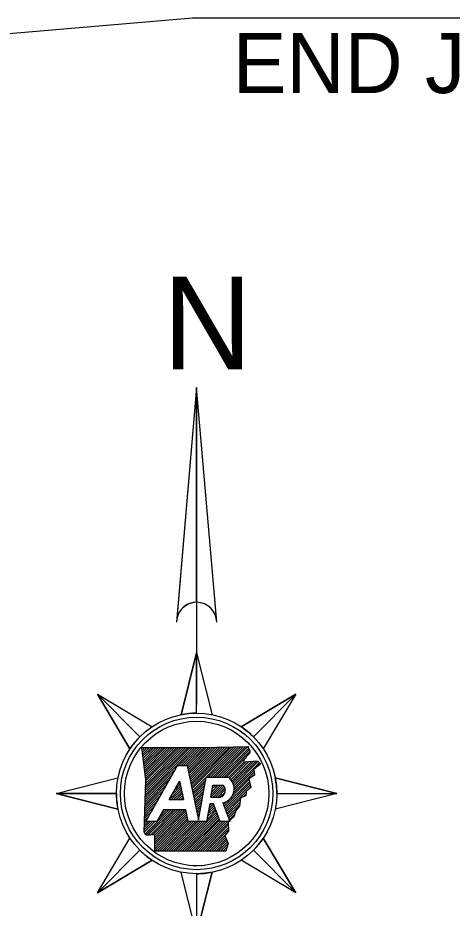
# Model space of a CAD drawing. Extents: x 1367863 to 1368197, y 380048 to 380261.
# Drawn here: x 1368103.87 to 1368125.53, y 380096.4 to 380140.77 of the extents above; entities that cross this region are included whole.
import ezdxf

# ---------------------------------------------------------------- set-up
doc = ezdxf.new("R2010")
doc.units = 0
doc.layers.add('R_Draft', color=7, linetype='Continuous')
doc.layers.add('R_Water Annot', color=7, linetype='Continuous')

msp = doc.modelspace()

# ---------------------------------------------------------------- linework, layer by layer
at = {"layer": 'R_Draft'}
for p, q in [((1368112.592, 380140.769), (1368153.505, 380140.769)), ((1368112.79, 380122.345), (1368111.804, 380110.815)), ((1368112.79, 380122.345), (1368112.79, 380106.554)), ((1368112.79, 380111.645), (1368112.79, 380122.345)), ((1368111.823, 380111.038), (1368111.915, 380111.129)), ((1368111.818, 380110.976), (1368111.863, 380111.021)), ((1368112.79, 380109.117), (1368112.011, 380106.041)), ((1368112.79, 380106.117), (1368112.79, 380109.117)), ((1368107.84, 380107.067), (1368109.961, 380104.946)), ((1368109.961, 380104.946), (1368107.84, 380107.067)), ((1368107.84, 380107.067), (1368109.465, 380104.341)), ((1368117.74, 380107.067), (1368115.013, 380105.442)), ((1368115.618, 380104.946), (1368117.74, 380107.067)), ((1368115.618, 380104.946), (1368117.74, 380107.067)), ((1368110.264, 380100.716), (1368111.842, 380103.503)), ((1368111.842, 380103.503), (1368112.311, 380103.503)), ((1368111.425, 380101.81), (1368111.941, 380102.722)), ((1368113.263, 380102.922), (1368114.359, 380102.922)), ((1368119.79, 380102.117), (1368116.713, 380102.896)), ((1368113.604, 380102.528), (1368114.119, 380102.528)), ((1368105.79, 380102.117), (1368108.79, 380102.117)), ((1368108.79, 380102.117), (1368105.79, 380102.117)), ((1368105.79, 380102.117), (1368108.866, 380101.338)), ((1368111.425, 380101.81), (1368112.136, 380101.81)), ((1368113.501, 380101.933), (1368113.971, 380101.933)), ((1368116.79, 380102.117), (1368119.79, 380102.117)), ((1368116.79, 380102.117), (1368119.79, 380102.117)), ((1368113.633, 380101.602), (1368113.443, 380101.602)), ((1368113.96, 380100.716), (1368113.633, 380101.602)), ((1368114.097, 380101.65), (1368114.442, 380100.716)), ((1368111.136, 380101.301), (1368110.805, 380100.716)), ((1368112.245, 380101.301), (1368111.136, 380101.301)), ((1368110.805, 380100.716), (1368110.264, 380100.716)), ((1368113.289, 380100.716), (1368112.37, 380100.716)), ((1368114.442, 380100.716), (1368113.96, 380100.716)), ((1368117.74, 380097.167), (1368116.115, 380099.894)), ((1368107.84, 380097.167), (1368109.961, 380099.289)), ((1368109.961, 380099.289), (1368107.84, 380097.167)), ((1368115.618, 380099.289), (1368117.74, 380097.167)), ((1368115.618, 380099.289), (1368117.74, 380097.167)), ((1368107.84, 380097.167), (1368110.566, 380098.792)), ((1368112.79, 380095.117), (1368113.569, 380098.194)), ((1368112.79, 380098.117), (1368112.79, 380098.117)), ((1368112.79, 380098.117), (1368112.79, 380085.312)), ((1368112.79, 380098.117), (1368112.79, 380095.117))]:
    msp.add_line(p, q, dxfattribs=at)
for points in [[(1368073.255, 380137.414), (1368112.592, 380140.769)], [(1368113.79, 380110.645), (1368112.79, 380122.345), (1368111.79, 380110.645)], [(1368112.011, 380106.041), (1368112.79, 380109.117), (1368113.569, 380106.041)], [(1368109.465, 380104.341), (1368107.84, 380107.067), (1368110.566, 380105.442)], [(1368115.013, 380105.442), (1368117.74, 380107.067), (1368116.115, 380104.341)], [(1368110.059, 380104.407), (1368111.62, 380104.406), (1368112.99, 380104.409), (1368114.605, 380104.434), (1368115.354, 380104.451)], [(1368110.172, 380100.184), (1368110.259, 380102.803), (1368110.059, 380104.407)], [(1368115.845, 380103.734), (1368115.98, 380103.593), (1368115.643, 380103.316), (1368115.679, 380103.037), (1368115.391, 380102.846), (1368115.49, 380102.417), (1368115.267, 380102.214), (1368115.247, 380101.993), (1368114.976, 380101.895), (1368114.934, 380101.479), (1368114.74, 380101.271), (1368114.646, 380100.957), (1368114.362, 380100.698), (1368114.384, 380100.24), (1368114.191, 380100.024), (1368114.367, 380099.632), (1368114.245, 380099.242)], [(1368115.123, 380103.698), (1368115.855, 380103.735)], [(1368112.311, 380103.503), (1368112.891, 380100.79), (1368113.263, 380102.922)], [(1368108.866, 380101.338), (1368105.79, 380102.117), (1368108.866, 380102.896)], [(1368111.941, 380102.722), (1368112.136, 380101.81)], [(1368116.713, 380102.896), (1368119.79, 380102.117), (1368116.713, 380101.338)], [(1368113.501, 380101.933), (1368113.604, 380102.528)], [(1368113.443, 380101.602), (1368113.289, 380100.716)], [(1368112.37, 380100.716), (1368112.245, 380101.301)], [(1368114.245, 380099.242), (1368110.708, 380099.248), (1368110.706, 380100.029)], [(1368110.566, 380098.792), (1368107.84, 380097.167), (1368109.465, 380099.894)], [(1368116.115, 380099.894), (1368117.74, 380097.167), (1368115.013, 380098.792)], [(1368113.569, 380098.194), (1368112.79, 380095.117), (1368112.011, 380098.194)]]:
    msp.add_lwpolyline(points, dxfattribs=at)
for radius in [4, 3.6]:
    msp.add_circle((1368112.79, 380102.117), radius, dxfattribs=at)
for centre, radius, start, end in [((1368112.79, 380110.645), 1, 0, 180), ((1368112.79, 380110.645), 1, 90, 170.2296), ((1368112.79, 380102.117), 4, 90, 101.2291), ((1368112.79, 380102.117), 4, 45, 56.2291), ((1368112.79, 380102.117), 4, 135, 146.2291), ((1368113.951, 380102.343), 0.708, 281.8626, 54.8705), ((1368112.79, 380102.117), 4, 0, 11.2291), ((1368113.858, 380102.277), 0.362, 288.1268, 43.8902), ((1368112.79, 380102.117), 4, 180, 191.2291), ((1368112.79, 380102.117), 4, 315, 326.2291), ((1368112.79, 380102.117), 4, 225, 236.2291), ((1368112.79, 380102.117), 4, 270, 281.2291)]:
    msp.add_arc(centre, radius, start, end, dxfattribs=at)
for points in [[(1368115.354, 380104.451), (1368115.359, 380104.409), (1368115.373, 380104.387), (1368115.375, 380104.346), (1368115.391, 380104.329), (1368115.419, 380104.311), (1368115.444, 380104.283), (1368115.45, 380104.251), (1368115.442, 380104.217), (1368115.44, 380104.179), (1368115.436, 380104.146), (1368115.431, 380104.116), (1368115.408, 380104.092), (1368115.385, 380104.075), (1368115.365, 380104.055), (1368115.351, 380104.033), (1368115.325, 380104.01), (1368115.3, 380103.986), (1368115.28, 380103.965), (1368115.26, 380103.938), (1368115.25, 380103.908), (1368115.228, 380103.887), (1368115.211, 380103.867), (1368115.187, 380103.841), (1368115.176, 380103.815), (1368115.154, 380103.785), (1368115.149, 380103.756), (1368115.134, 380103.733), (1368115.133, 380103.729)], [(1368110.706, 380100.029), (1368110.71, 380100.027), (1368110.691, 380100.039), (1368110.666, 380100.052), (1368110.638, 380100.054), (1368110.602, 380100.058), (1368110.572, 380100.061), (1368110.542, 380100.082), (1368110.509, 380100.06), (1368110.472, 380100.045), (1368110.451, 380100.062), (1368110.423, 380100.051), (1368110.404, 380100.057), (1368110.37, 380100.033), (1368110.338, 380100.042), (1368110.315, 380100.035), (1368110.286, 380100.036), (1368110.28, 380100.069), (1368110.252, 380100.074), (1368110.228, 380100.087), (1368110.211, 380100.121), (1368110.2, 380100.147), (1368110.172, 380100.184)]]:
    msp.add_spline(points, degree=3, dxfattribs=at)
at = {"layer": 'R_Water Annot'}
for p, q in [((1368112.42, 380102.995), (1368113.847, 380104.422)), ((1368112.44, 380102.901), (1368113.962, 380104.424)), ((1368112.46, 380102.808), (1368114.077, 380104.426)), ((1368112.48, 380102.715), (1368114.192, 380104.428)), ((1368112.499, 380102.622), (1368114.307, 380104.429)), ((1368112.519, 380102.529), (1368114.422, 380104.431)), ((1368112.539, 380102.435), (1368114.537, 380104.433)), ((1368112.559, 380102.342), (1368114.652, 380104.435)), ((1368112.579, 380102.249), (1368114.768, 380104.438)), ((1368113.365, 380102.922), (1368114.884, 380104.44)), ((1368113.478, 380102.922), (1368115, 380104.443)), ((1368113.591, 380102.922), (1368115.116, 380104.446)), ((1368113.705, 380102.922), (1368115.231, 380104.449)), ((1368113.818, 380102.922), (1368115.347, 380104.451)), ((1368110.063, 380104.372), (1368110.099, 380104.407)), ((1368110.076, 380104.271), (1368110.212, 380104.407)), ((1368110.088, 380104.17), (1368110.325, 380104.407)), ((1368110.101, 380104.07), (1368110.438, 380104.407)), ((1368110.113, 380103.969), (1368110.551, 380104.407)), ((1368110.126, 380103.869), (1368110.664, 380104.407)), ((1368110.139, 380103.768), (1368110.777, 380104.407)), ((1368110.151, 380103.667), (1368110.89, 380104.406)), ((1368110.164, 380103.567), (1368111.003, 380104.406)), ((1368110.176, 380103.466), (1368111.116, 380104.406)), ((1368110.189, 380103.366), (1368111.229, 380104.406)), ((1368110.201, 380103.265), (1368111.342, 380104.406)), ((1368110.214, 380103.164), (1368111.455, 380104.406)), ((1368110.226, 380103.064), (1368111.568, 380104.406)), ((1368110.23, 380101.936), (1368112.702, 380104.408)), ((1368110.234, 380102.053), (1368112.589, 380104.408)), ((1368110.238, 380102.17), (1368112.475, 380104.408)), ((1368110.239, 380102.963), (1368111.682, 380104.406)), ((1368110.242, 380102.287), (1368112.362, 380104.408)), ((1368110.246, 380102.404), (1368112.249, 380104.407)), ((1368110.249, 380102.521), (1368112.135, 380104.407)), ((1368110.251, 380102.863), (1368111.795, 380104.406)), ((1368110.253, 380102.638), (1368112.022, 380104.407)), ((1368110.257, 380102.755), (1368111.908, 380104.407)), ((1368111.91, 380103.503), (1368112.815, 380104.409)), ((1368112.023, 380103.503), (1368112.929, 380104.409)), ((1368112.136, 380103.503), (1368113.043, 380104.41)), ((1368112.25, 380103.503), (1368113.158, 380104.412)), ((1368112.32, 380103.461), (1368113.273, 380104.413)), ((1368112.34, 380103.367), (1368113.388, 380104.415)), ((1368112.36, 380103.274), (1368113.503, 380104.417)), ((1368112.38, 380103.181), (1368113.618, 380104.419)), ((1368112.4, 380103.088), (1368113.733, 380104.42)), ((1368113.931, 380102.922), (1368115.372, 380104.363)), ((1368114.044, 380102.922), (1368115.427, 380104.305)), ((1368114.157, 380102.922), (1368115.442, 380104.206)), ((1368114.27, 380102.922), (1368115.183, 380103.835)), ((1368114.373, 380102.911), (1368115.161, 380103.7)), ((1368114.435, 380102.86), (1368115.28, 380103.706)), ((1368114.49, 380102.802), (1368115.4, 380103.712)), ((1368114.539, 380102.738), (1368115.519, 380103.718)), ((1368114.581, 380102.667), (1368115.638, 380103.724)), ((1368114.615, 380102.588), (1368115.757, 380103.73)), ((1368114.641, 380102.501), (1368115.865, 380103.724)), ((1368114.657, 380102.403), (1368115.918, 380103.664)), ((1368115.868, 380103.501), (1368115.971, 380103.604)), ((1368110.226, 380101.819), (1368111.753, 380103.346)), ((1368114.634, 380102.154), (1368115.661, 380103.181)), ((1368114.658, 380102.291), (1368115.648, 380103.281)), ((1368110.218, 380101.585), (1368111.457, 380102.824)), ((1368110.222, 380101.702), (1368111.605, 380103.085)), ((1368111.861, 380102.58), (1368111.952, 380102.671)), ((1368112.599, 380102.156), (1368113.241, 380102.798)), ((1368112.619, 380102.063), (1368113.217, 380102.661)), ((1368114.167, 380101.461), (1368115.421, 380102.715)), ((1368114.535, 380101.942), (1368115.4, 380102.807)), ((1368115.534, 380102.941), (1368115.674, 380103.081)), ((1368110.211, 380101.351), (1368111.162, 380102.303)), ((1368110.214, 380101.468), (1368111.31, 380102.563)), ((1368111.43, 380101.81), (1368112.011, 380102.391)), ((1368111.543, 380101.81), (1368112.031, 380102.298)), ((1368111.565, 380102.058), (1368111.992, 380102.485)), ((1368111.656, 380101.81), (1368112.051, 380102.205)), ((1368111.713, 380102.319), (1368111.972, 380102.578)), ((1368112.639, 380101.969), (1368113.193, 380102.524)), ((1368112.659, 380101.876), (1368113.17, 380102.387)), ((1368112.679, 380101.783), (1368113.146, 380102.25)), ((1368113.501, 380101.933), (1368114.097, 380102.528)), ((1368113.524, 380102.069), (1368113.983, 380102.528)), ((1368113.548, 380102.206), (1368113.87, 380102.528)), ((1368113.572, 380102.343), (1368113.757, 380102.528)), ((1368113.596, 380102.48), (1368113.644, 380102.528)), ((1368113.614, 380101.933), (1368114.159, 380102.478)), ((1368113.728, 380101.933), (1368114.198, 380102.403)), ((1368113.841, 380101.933), (1368114.219, 380102.311)), ((1368114.197, 380101.378), (1368115.442, 380102.623)), ((1368114.228, 380101.295), (1368115.463, 380102.531)), ((1368114.258, 380101.213), (1368115.484, 380102.439)), ((1368110.203, 380101.117), (1368110.867, 380101.781)), ((1368110.207, 380101.234), (1368111.014, 380102.042)), ((1368111.769, 380101.81), (1368112.071, 380102.112)), ((1368111.883, 380101.81), (1368112.091, 380102.019)), ((1368111.996, 380101.81), (1368112.111, 380101.925)), ((1368112.109, 380101.81), (1368112.131, 380101.832)), ((1368112.699, 380101.69), (1368113.122, 380102.113)), ((1368112.719, 380101.597), (1368113.098, 380101.976)), ((1368112.739, 380101.503), (1368113.074, 380101.839)), ((1368113.954, 380101.933), (1368114.209, 380102.188)), ((1368114.289, 380101.13), (1368114.968, 380101.809)), ((1368115.098, 380101.939), (1368115.256, 380102.098)), ((1368110.199, 380101), (1368110.719, 380101.52)), ((1368112.759, 380101.41), (1368113.05, 380101.702)), ((1368112.779, 380101.317), (1368113.026, 380101.565)), ((1368112.799, 380101.224), (1368113.002, 380101.428)), ((1368113.332, 380100.965), (1368113.724, 380101.357)), ((1368113.356, 380101.102), (1368113.693, 380101.44)), ((1368113.38, 380101.239), (1368113.663, 380101.522)), ((1368113.404, 380101.376), (1368113.63, 380101.602)), ((1368113.427, 380101.513), (1368113.517, 380101.602)), ((1368114.106, 380101.626), (1368114.14, 380101.66)), ((1368114.136, 380101.543), (1368114.352, 380101.759)), ((1368114.319, 380101.048), (1368114.955, 380101.683)), ((1368114.35, 380100.965), (1368114.942, 380101.557)), ((1368110.191, 380100.766), (1368110.424, 380100.998)), ((1368110.195, 380100.883), (1368110.571, 380101.259)), ((1368110.216, 380100.112), (1368111.405, 380101.301)), ((1368110.283, 380100.066), (1368111.518, 380101.301)), ((1368110.364, 380100.034), (1368111.631, 380101.301)), ((1368110.499, 380100.055), (1368111.744, 380101.301)), ((1368110.613, 380100.057), (1368111.857, 380101.301)), ((1368110.702, 380100.032), (1368111.97, 380101.301)), ((1368110.706, 380099.81), (1368112.197, 380101.301)), ((1368110.706, 380099.923), (1368112.084, 380101.301)), ((1368110.706, 380099.697), (1368112.256, 380101.247)), ((1368110.707, 380099.585), (1368112.276, 380101.154)), ((1368110.707, 380099.472), (1368112.296, 380101.061)), ((1368110.707, 380099.359), (1368112.316, 380100.968)), ((1368110.709, 380099.248), (1368112.336, 380100.874)), ((1368110.933, 380100.943), (1368111.292, 380101.301)), ((1368111.081, 380101.203), (1368111.179, 380101.301)), ((1368111.839, 380099.246), (1368113.785, 380101.192)), ((1368111.952, 380099.246), (1368113.815, 380101.109)), ((1368112.065, 380099.245), (1368113.846, 380101.026)), ((1368112.178, 380099.245), (1368113.876, 380100.944)), ((1368112.819, 380101.131), (1368112.979, 380101.291)), ((1368112.839, 380101.037), (1368112.955, 380101.154)), ((1368112.858, 380100.944), (1368112.931, 380101.017)), ((1368112.878, 380100.851), (1368112.907, 380100.88)), ((1368113.308, 380100.828), (1368113.754, 380101.274)), ((1368114.38, 380100.882), (1368114.727, 380101.229)), ((1368114.411, 380100.8), (1368114.679, 380101.068)), ((1368110.174, 380100.183), (1368110.707, 380100.716)), ((1368110.176, 380100.298), (1368110.594, 380100.716)), ((1368110.18, 380100.415), (1368110.481, 380100.716)), ((1368110.183, 380100.532), (1368110.367, 380100.716)), ((1368110.187, 380100.649), (1368110.276, 380100.738)), ((1368110.822, 380099.247), (1368112.356, 380100.781)), ((1368110.935, 380099.247), (1368112.404, 380100.716)), ((1368111.048, 380099.247), (1368112.517, 380100.716)), ((1368111.161, 380099.247), (1368112.63, 380100.716)), ((1368111.274, 380099.247), (1368112.743, 380100.716)), ((1368111.387, 380099.247), (1368112.856, 380100.716)), ((1368111.5, 380099.246), (1368112.97, 380100.716)), ((1368111.613, 380099.246), (1368113.083, 380100.716)), ((1368111.726, 380099.246), (1368113.196, 380100.716)), ((1368112.291, 380099.245), (1368113.907, 380100.861)), ((1368112.404, 380099.245), (1368113.937, 380100.779)), ((1368112.516, 380099.245), (1368113.988, 380100.716)), ((1368112.629, 380099.244), (1368114.101, 380100.716)), ((1368112.742, 380099.244), (1368114.214, 380100.716)), ((1368112.855, 380099.244), (1368114.327, 380100.716)), ((1368112.968, 380099.244), (1368114.365, 380100.641)), ((1368113.081, 380099.244), (1368114.37, 380100.533)), ((1368113.194, 380099.244), (1368114.375, 380100.425)), ((1368113.307, 380099.243), (1368114.38, 380100.317)), ((1368113.42, 380099.243), (1368114.194, 380100.018)), ((1368113.533, 380099.243), (1368114.229, 380099.939)), ((1368113.646, 380099.243), (1368114.264, 380099.861)), ((1368113.759, 380099.243), (1368114.299, 380099.783)), ((1368113.872, 380099.242), (1368114.334, 380099.705)), ((1368113.985, 380099.242), (1368114.363, 380099.621)), ((1368114.098, 380099.242), (1368114.312, 380099.456)), ((1368114.211, 380099.242), (1368114.261, 380099.292))]:
    msp.add_line(p, q, dxfattribs=at)
msp.add_circle((1368112.79, 380102.117), 3.8, dxfattribs=at)

# ---------------------------------------------------------------- texts
at = {"layer": 'R_Draft'}
for s, height, p in [('END JOB 061609', 3, (1368114.595, 380137.019)), ('N', 4.615, (1368111.103, 380123.253)), ('DWB 7-27-17', 0.07778, (1368112.545, 380098.451))]:
    msp.add_text(s, height=height, dxfattribs=at).set_placement(p)

doc.saveas('drawing.dxf')
